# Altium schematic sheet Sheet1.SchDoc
size A3
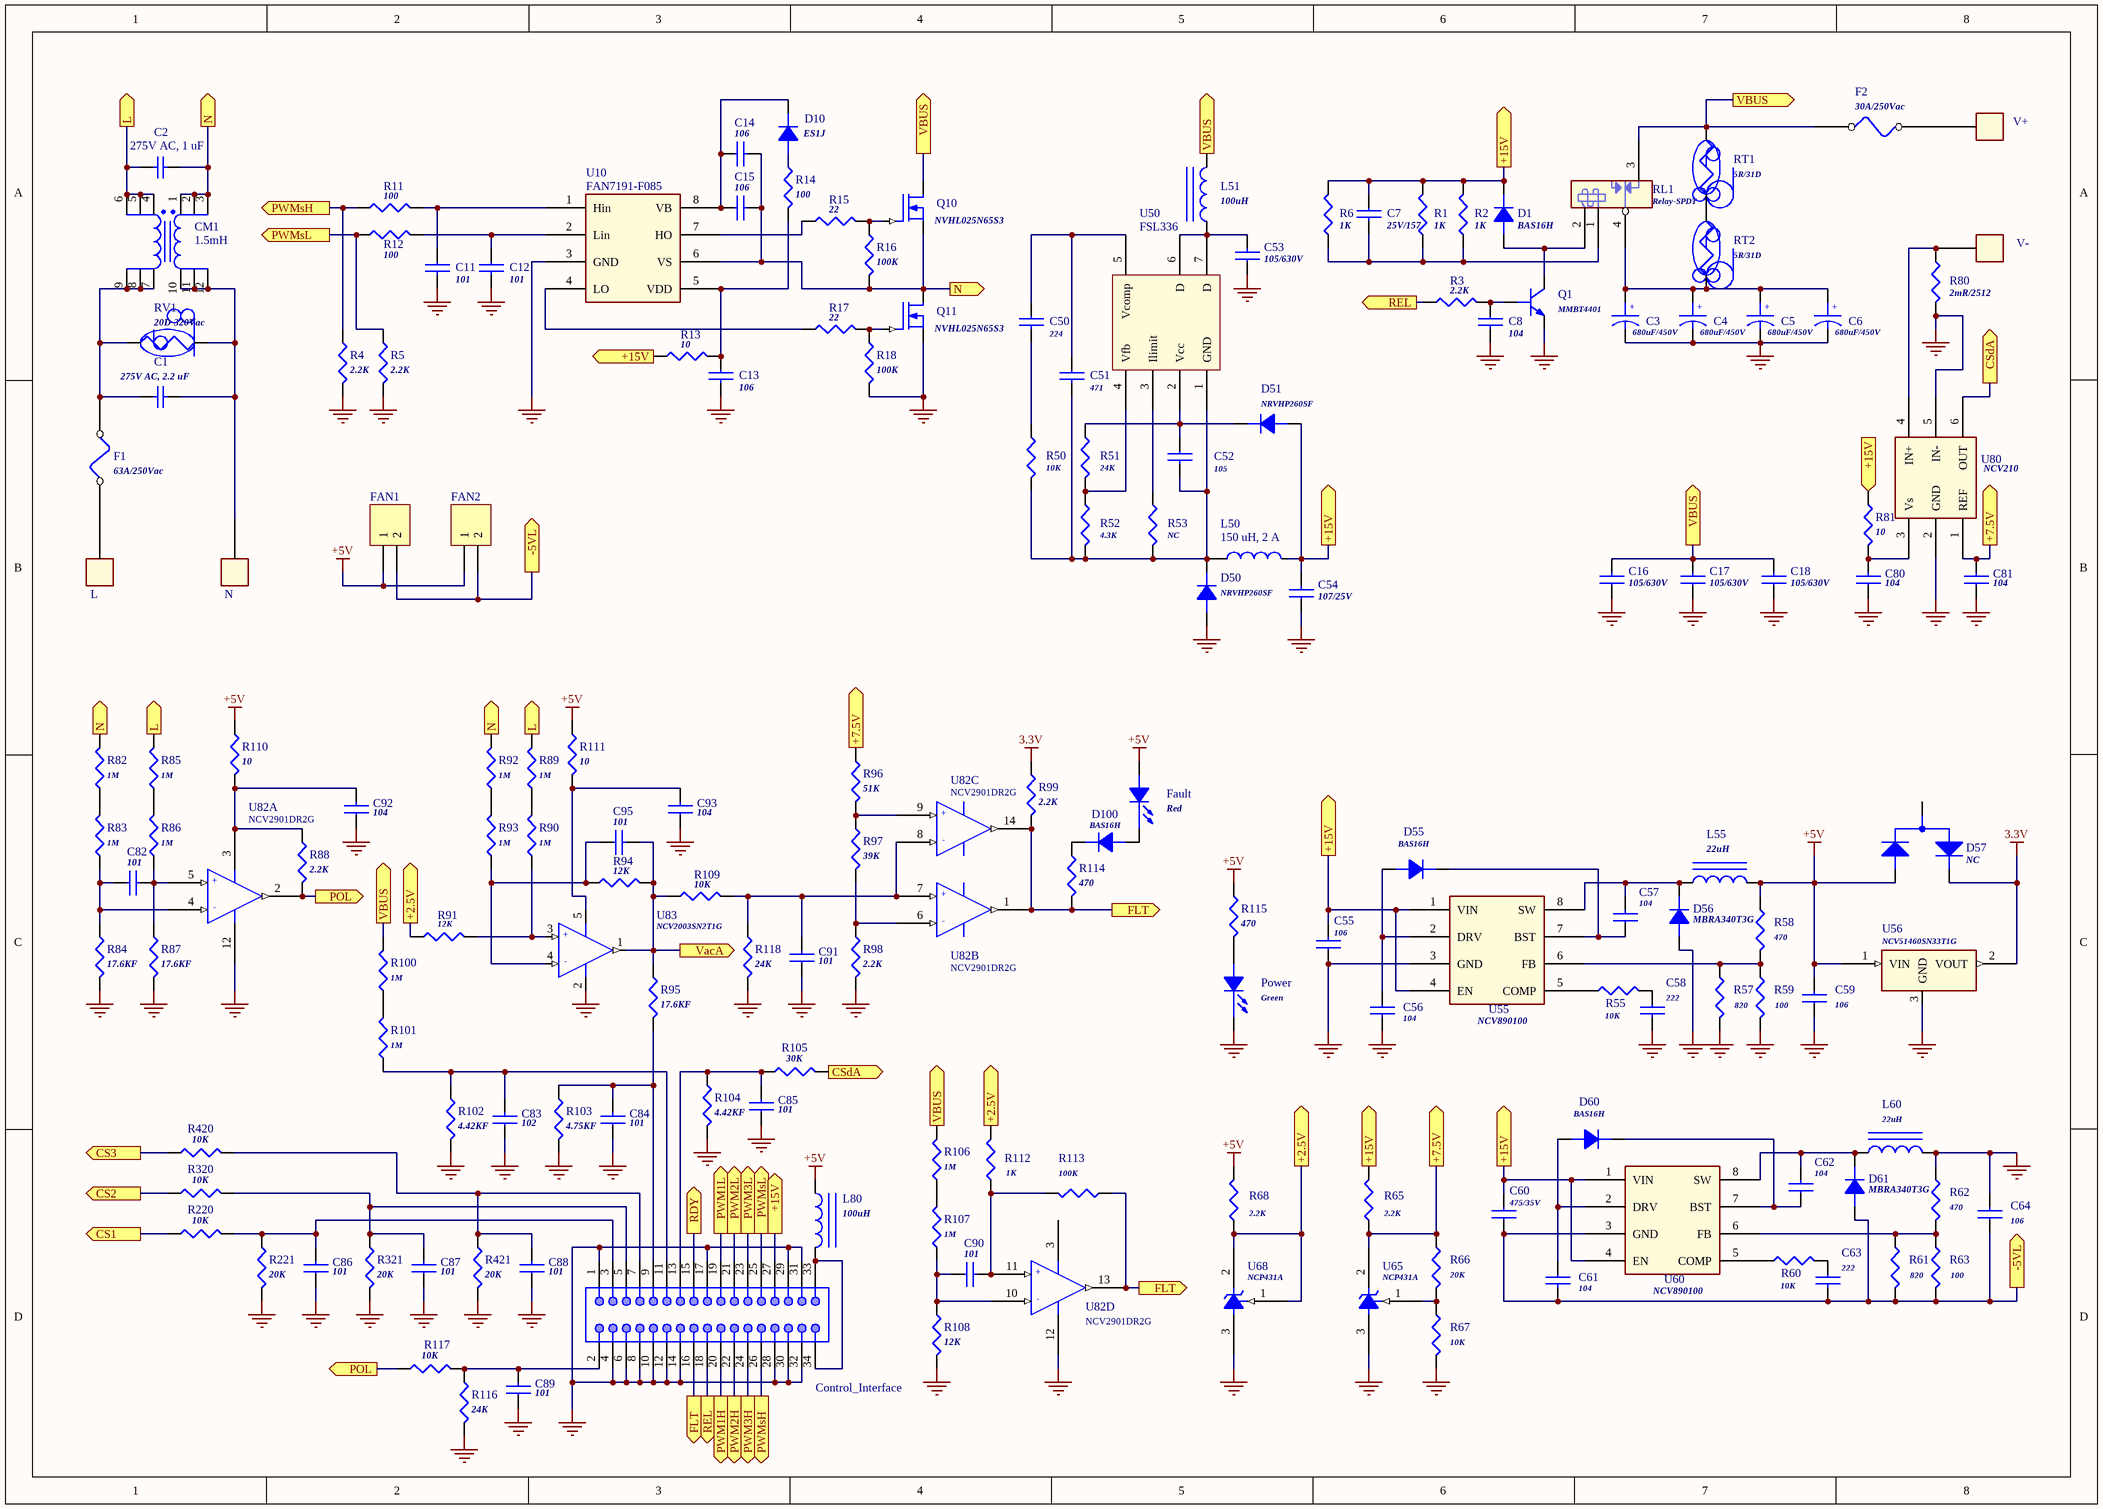
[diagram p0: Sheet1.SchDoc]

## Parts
C1  275V AC, 2.2 uF  [WCAP-FTX2_26x15x25_CS]
C2  275V AC, 1 uF  [WCAP-FTX2_26x11x20_CS]
C3  680uF/450V  [WCAP-AI3H_35x57]
C4  680uF/450V  [WCAP-AI3H_35x57]
C5  680uF/450V  [WCAP-AI3H_35x57]
C6  680uF/450V  [WCAP-AI3H_35x57]
C7  25V/157  [CAP2220_3]
C8  104  [SMT_0805_CM]
C11  101  [SMT_0805_CM]
C12  101  [SMT_0805_CM]
C13  106  [SMT_1206_CM]
C14  106  [SMT_1206_CM]
C15  106  [SMT_1206_CM]
C16  105/630V  [CAP2220]
C17  105/630V  [CAP2220]
C18  105/630V  [CAP2220]
C50  224  [SMT_0805_CM]
C51  471  [SMT_0805_CM]
C52  105  [SMT_0805_CM]
C53  105/630V  [CAP2220]
C54  107/25V  [CAP2220]
C55  106  [SMT_1206_CM]
C56  104  [SMT_0805_CM]
C57  104  [SMT_0805_CM]
C58  222  [SMT_0805_CM]
C59  106  [SMT_1206_CM]
C60  475/35V  [SMT_1206_CM]
C61  104  [SMT_0805_CM]
C62  104  [SMT_0805_CM]
C63  222  [SMT_0805_CM]
C64  106  [SMT_1206_CM]
C80  104  [SMT_0805_CM]
C81  104  [SMT_0805_CM]
C82  101  [SMT_0805_CM]
C83  102  [SMT_0805_CM]
C84  101  [SMT_0805_CM]
C85  101  [SMT_0805_CM]
C86  101  [SMT_0805_CM]
C87  101  [SMT_0805_CM]
C88  101  [SMT_0805_CM]
C89  101  [SMT_0805_CM]
C90  101  [SMT_0805_CM]
C91  101  [SMT_0805_CM]
C92  104  [SMT_0805_CM]
C93  104  [SMT_0805_CM]
C95  101  [SMT_0805_CM]
CM1  1.5mH  [L-WE-CMBNC_Type XXL_7448063801]
Control_Interface  (no value)  [61203421621]
D1  BAS16H  [SOD-323M]
D10  ES1J  [DO-214AC(SMA)]
D50  NRVHP260SF  [SOD-123FL]
D51  NRVHP260SF  [SOD-123FL]
D55  BAS16H  [SOD-323]
D56  MBRA340T3G  [DO-214AC(SMA)]
D57  NC  [SOT-23-3L]
D60  BAS16H  [SOD-323]
D61  MBRA340T3G  [DO-214AC(SMA)]
D100  BAS16H  [SOD-323]
F1  63A/250Vac  [Fuse_63A]
F2  30A/250Vac  [FUSE-L]
FAN1  Header 2  [XH-2A]  (value not drawn)
FAN2  Header 2  [XH-2A]  (value not drawn)
Fault  Red  [LED 5MM-R]
L  (no value)  [TermL]
L50  150 uH, 2 A  [WE-TI_1014_Standard]
L51  100uH  [Bead_1210]
L55  22uH  [INDUCTOR-7*7*3.5]
L60  22uH  [INDUCTOR-7*7*3.5]
L80  100uH  [Bead_1210]
N  (no value)  [TermL]
Power  Green  [LED 5MM-R]
Q1  MMBT4401  [SOT-23-3L]
Q10  NVHL025N65S3  [TO247]
Q11  NVHL025N65S3  [TO247]
R1  1K  [SMT_1206_RM]
R2  1K  [SMT_1206_RM]
R3  2.2K  [SMT_0805_RM]
R4  2.2K  [SMT_0805_RM]
R5  2.2K  [SMT_0805_RM]
R6  1K  [SMT_1206_RM]
R11  100  [SMT_0805_RM]
R12  100  [SMT_0805_RM]
R13  10  [SMT_0805_RM]
R14  100  [SMT_0805_RM]
R15  22  [SMT_0805_RM]
R16  100K  [SMT_0805_RM]
R17  22  [SMT_0805_RM]
R18  100K  [SMT_0805_RM]
R50  10K  [SMT_0805_RM]
R51  24K  [SMT_0805_RM]
R52  4.3K  [SMT_0805_RM]
R53  NC  [SMT_0805_RM]
R55  10K  [SMT_0805_RM]
R57  820  [SMT_0805_RM]
R58  470  [SMT_0805_RM]
R59  100  [SMT_0805_RM]
R60  10K  [SMT_0805_RM]
R61  820  [SMT_0805_RM]
R62  470  [SMT_0805_RM]
R63  100  [SMT_0805_RM]
R65  2.2K  [SMT_1206_RM]
R66  20K  [SMT_0805_RM]
R67  10K  [SMT_0805_RM]
R68  2.2K  [SMT_0805_RM]
R80  2mR/2512  [SMT_2512_R]
R81  10  [SMT_0805_RM]
R82  1M  [SMT_1206_RM]
R83  1M  [SMT_1206_RM]
R84  17.6KF  [SMT_0805_RM]
R85  1M  [SMT_1206_RM]
R86  1M  [SMT_1206_RM]
R87  17.6KF  [SMT_0805_RM]
R88  2.2K  [SMT_0805_RM]
R89  1M  [SMT_1206_RM]
R90  1M  [SMT_1206_RM]
R91  12K  [SMT_0805_RM]
R92  1M  [SMT_1206_RM]
R93  1M  [SMT_1206_RM]
R94  12K  [SMT_0805_RM]
R95  17.6KF  [SMT_0805_RM]
R96  51K  [SMT_0805_RM]
R97  39K  [SMT_0805_RM]
R98  2.2K  [SMT_0805_RM]
R99  2.2K  [SMT_0805_RM]
R100  1M  [SMT_1206_RM]
R101  1M  [SMT_1206_RM]
R102  4.42KF  [SMT_0805_RM]
R103  4.75KF  [SMT_0805_RM]
R104  4.42KF  [SMT_0805_RM]
R105  30K  [SMT_0805_RM]
R106  1M  [SMT_1206_RM]
R107  1M  [SMT_1206_RM]
R108  12K  [SMT_0805_RM]
R109  10K  [SMT_0805_RM]
R110  10  [SMT_0805_RM]
R111  10  [SMT_0805_RM]
R112  1K  [SMT_0805_RM]
R113  100K  [SMT_0805_RM]
R114  470  [SMT_0805_RM]
R115  470  [SMT_0805_RM]
R116  24K  [SMT_0805_RM]
R117  10K  [SMT_0805_RM]
R118  24K  [SMT_0805_RM]
R220  10K  [SMT_0805_RM]
R221  20K  [SMT_0805_RM]
R320  10K  [SMT_0805_RM]
R321  20K  [SMT_0805_RM]
R420  10K  [SMT_0805_RM]
R421  20K  [SMT_0805_RM]
RL1  Relay-SPDT  [Relay- SPST-25A]
RT1  5R/31D  [NTC-D31]
RT2  5R/31D  [NTC-D31]
RV1  20D-320Vac  [Thermistor-20mm-2]
U10  FAN7191-F085  [Sop8]
U50  FSL336  [DIP7]
U55  NCV890100  [SOIC8E]
U56  NCV51460SN33T1G  [SOT-23-3L]
U60  NCV890100  [SOIC8E]
U65  NCP431A  [SOT-23-3L]
U68  NCP431A  [SOT-23-3L]
U80  NCV210  [SC70-6]
U82  NCV2901DR2G  [SOP14]  (parts A,B,C,D of 4)
U83  NCV2003SN2T1G  [SOT-23-5L]
V+  (no value)  [TermL]
V-  (no value)  [TermL]

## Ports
+2.5V (out), +7.5V (out), +15V (out), -5VL (out), CS1 (out), CS2 (out), CS3 (out), CSdA (out), FLT (out), L (out), N (out), POL (out), PWM1H (out), PWM1L (out), PWM2H (out), PWM2L (out), PWM3H (out), PWM3L (out), PWMsH (out), PWMsL (out), RDY (out), REL (out), VacA (out), VBUS (out)

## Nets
3.3V: D57.2 R99.1 U56.2(VOUT)
+5V: C59.2 D57.1 FAN1.1 FAN2.1 Fault.1(ANODE) L55.2 L80.1 R58.1 R68.2 R110.1 R111.1 R115.1 U56.1(VIN)
PGND: C3.2 C4.2 C5.2 C6.2 C8.2 C11.2 C12.2 C13.2 C16.1 C17.1 C18.1 C53.1 C54.1 C55.1 C56.2 C58.2 C59.1 C64.2 C80.1 C81.1 C83.1 C84.1 C85.1 C86.1 C87.1 C88.1 C89.1 C91.1 C92.1 C93.1 Control_Interface.1 Control_Interface.4 Control_Interface.6 Control_Interface.8 Control_Interface.10 Control_Interface.12 Control_Interface.14 Control_Interface.17 Control_Interface.28 Control_Interface.29 Control_Interface.30 Control_Interface.31 Control_Interface.32 D50.1(A) D56.1(A) L60.2 Power.2(CATHODE) Q1.2(E) Q11.3(SOURCE) R4.2 R5.2 R18.2 R57.2 R59.2 R62.1 R67.2 R80.2 R84.2 R87.2 R98.2 R102.2 R103.2 R104.2 R108.2 R116.2 R118.2 R221.2 R321.2 R421.2 U10.3(GND) U55.3(GND) U56.3(GND) U65.3(A) U68.3(A) U80.2(GND) U80.5(IN-) U82.12(GND) U83.2(GND)
+2.5V: R68.1 R91.1 R112.2 U68.1(REF) U68.2(K) ; port +2.5V
+7.5V: C81.2 R65.1 R66.1 R96.1 U65.2(K) U80.1(REF) ; port +7.5V
+15V: C7.1 C54.2 C55.2 C60.2 Control_Interface.27 D1.2(K) D51.1(A) L50.2 R1.2 R2.2 R6.2 R13.1 R65.2 R81.1 U55.1(VIN) U55.4(EN) U60.1(VIN) U60.4(EN) ; port +15V
-5VL: C60.1 C61.2 C63.2 C64.1 D61.1(A) FAN1.2 FAN2.2 R61.2 R63.2 U60.3(GND) ; port -5VL
CS1: R220.1 ; port CS1
CS2: R320.1 ; port CS2
CS3: R420.1 ; port CS3
CSdA: R105.2 U80.6(OUT) ; port CSdA
FLT: Control_Interface.16 R99.2 R113.1 R114.2 U82.1(OUT) U82.13(OUT) U82.14(OUT) ; port FLT
L: C2.2 CM1.4 CM1.5 CM1.6 R85.2 R89.2 ; port L
N: C2.1 C14.2 C15.2 CM1.1 CM1.2 CM1.3 Q10.3(SOURCE) Q11.2(DRAIN) R16.2 R82.2 R92.2 U10.6(VS) ; port N
POL: R88.2 R117.1 U82.2(OUT) ; port POL
PWM1H: Control_Interface.20 ; port PWM1H
PWM1L: Control_Interface.19 ; port PWM1L
PWM2H: Control_Interface.22 ; port PWM2H
PWM2L: Control_Interface.21 ; port PWM2L
PWM3H: Control_Interface.24 ; port PWM3H
PWM3L: Control_Interface.23 ; port PWM3L
PWMsH: Control_Interface.26 R4.1 R11.1 ; port PWMsH
PWMsL: Control_Interface.25 R5.1 R12.1 ; port PWMsL
RDY: Control_Interface.15 ; port RDY
REL: Control_Interface.18 R3.1 ; port REL
VacA: C95.2 R94.2 R95.1 R109.1 U83.1(OUT) ; port VacA
VBUS: C16.2 C17.2 C18.2 F2.1 L51.2 Q10.2(DRAIN) R100.2 R106.2 RL1.3(NO) RT1.1 ; port VBUS
NetC1_1: C1.1 CM1.10 CM1.11 CM1.12 N.1 RV1.2
NetC1_2: C1.2 CM1.7 CM1.8 CM1.9 F1.1 RV1.1
NetC3_1: C3.1 C4.1 C5.1 C6.1 RL1.4(COMMON) RT2.2
NetC7_2: C7.2 R1.1 R2.1 R6.1 RL1.1(COIL1)
NetC8_1: C8.1 Q1.1(B) R3.2
NetC11_1: C11.1 R11.2 U10.1(Hin)
NetC12_1: C12.1 R12.2 U10.2(Lin)
NetC13_1: C13.1 R13.2 R14.2 U10.5(VDD)
NetC14_1: C14.1 C15.1 D10.2(K) U10.8(VB)
NetC50_1: C50.1 C51.1 U50.5(Vcomp)
NetC50_2: C50.2 R50.1
NetC51_2: C51.2 C52.2 D50.2(K) L50.1 R50.2 R52.2 R53.2 U50.1(GND)
NetC52_1: C52.1 D51.2(K) R51.1 U50.2(Vcc)
NetC53_2: C53.2 L51.1 U50.6(D) U50.7(D)
NetC56_1: C56.1 D55.1(A) U55.2(DRV)
NetC57_1: C57.1 D55.2(K) U55.7(BST)
NetC57_2: C57.2 D56.2(K) L55.1 U55.8(SW)
NetC58_1: C58.1 R55.2
NetC61_1: C61.1 D60.1(A) U60.2(DRV)
NetC62_1: C62.1 D60.2(K) U60.7(BST)
NetC62_2: C62.2 D61.2(K) L60.1 U60.8(SW)
NetC63_1: C63.1 R60.2
NetC80_2: C80.2 R81.2 U80.3(Vs)
NetC82_1: C82.1 R83.1 R84.1 U82.4(-IN)
NetC82_2: C82.2 R86.1 R87.1 U82.5(+IN)
NetC83_2: C83.2 Control_Interface.11 R101.1 R102.1
NetC84_2: C84.2 Control_Interface.9 R95.2 R103.1
NetC85_2: C85.2 Control_Interface.13 R104.1 R105.1
NetC86_2: C86.2 Control_Interface.3 R220.2 R221.1
NetC87_2: C87.2 Control_Interface.5 R320.2 R321.1
NetC88_2: C88.2 Control_Interface.7 R420.2 R421.1
NetC89_2: C89.2 Control_Interface.2 R116.1 R117.2
NetC90_1: C90.1 R107.1 R108.1 U82.10(-IN)
NetC90_2: C90.2 R112.1 R113.2 U82.11(+IN)
NetC91_2: C91.2 R109.2 R118.1 U82.7(+IN) U82.8(-IN)
NetC92_2: C92.2 R88.1 R110.2 U82.3(VCC)
NetC93_2: C93.2 R111.2 U83.5(VCC)
NetC95_1: C95.1 R93.1 R94.1 U83.4(-IN)
NetControl_Interface_33: Control_Interface.33 Control_Interface.34 L80.2
NetD1_1: D1.1(A) Q1.3(C) RL1.2(COIL2)
NetD10_1: D10.1(A) R14.1
NetD100_1: D100.1(A) Fault.2(CATHODE)
NetD100_2: D100.2(K) R114.1
NetF1_2: F1.2 L.1
NetF2_2: F2.2 V+.1
NetPower_1: Power.1(ANODE) R115.2
NetQ10_1: Q10.1(GATE) R15.2 R16.1
NetQ11_1: Q11.1(GATE) R17.2 R18.1
NetR15_1: R15.1 U10.7(HO)
NetR17_1: R17.1 U10.4(LO)
NetR51_2: R51.2 R52.1 U50.4(Vfb)
NetR53_1: R53.1 U50.3(Ilimit)
NetR55_1: R55.1 U55.5(COMP)
NetR57_1: R57.1 R58.2 R59.1 U55.6(FB)
NetR60_1: R60.1 U60.5(COMP)
NetR61_1: R61.1 R62.2 R63.1 U60.6(FB)
NetR66_2: R66.2 R67.1 U65.1(REF)
NetR80_1: R80.1 U80.4(IN+) V-.1
NetR82_1: R82.1 R83.2
NetR85_1: R85.1 R86.2
NetR89_1: R89.1 R90.2
NetR90_1: R90.1 R91.2 U83.3(+IN)
NetR92_1: R92.1 R93.2
NetR96_2: R96.2 R97.1 U82.9(+IN)
NetR97_2: R97.2 R98.1 U82.6(-IN)
NetR100_1: R100.1 R101.2
NetR106_1: R106.1 R107.2
NetRT1_2: RT1.2 RT2.1

Not connected (* = marked no-connect by the designer): D57 3

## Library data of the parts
C1 = 890324026034CS: WCAP-FTX2 Film Capacitors, 26x15x25mm, 275V AC, 2.2 uF; Rated Voltage: 275V AC; Value: 2.2 uF
C2 = 890324026027CS: WCAP-FTX2 Film Capacitors, 26x11x20mm, 275V AC, 1 uF; Rated Voltage: 275V AC; Value: 1 uF
C3-C6 = CAP POL
C7 C8 C11-C18 C50-C64 C82 C90 C95 = CAP NP
C80 C81 C83-C89 C91-C93 = CAP_0805
CM1 = WE-CMBNC, 7448063801: WE-CMBNC Common Mode Power Line Choke Nanocrystalline, Type XXL, 1.5mH
Control_Interface = 61203421621: Male Box Header WR-BHD, THT, Vertical, pitch 2.54 mm, 34 pins; Pin Number: 34; Pitch: 2.54 mm; Working Voltage: 250 VAC; Withstanding Voltage: 500 VAC; Contact Resistance: 20 mOhm
D1 D50 D51 D55 D56 D60 D61 D100 = DIODE
D10 = D_SMA(DO-214AC)
D57 = BAT54S/SOT
F1 F2 = FUSE
FAN1 FAN2 = Header 2: Header, 2-Pin
Fault Power = LED
L N V+ V- = P_1
L50 = 7447480151: Radial Leaded Wire Wound Inductor WE-TI, size 1014, 150 uH, 2 A; Rated Current: 2 A; Inductance: 150 uH; DC Resistance max.: 0.18 Ohm; Self Resonant Frequency: 3.1 MHz; Saturation Current: 2.1 A; Type: Standard
L51 L55 L60 L80 = INDUCTOR IRON
Q1 = NPN BCE
Q10 Q11 = MOSFET N: NTPF082N65S3F; R187: C158
R1-R6 R11-R18 R55 R57-R63 R65-R68 R80-R104 R106-R116 R118 R221 R321 R421 = R
R50-R53 = R: D5: L20
R105 R117 R220 R320 R420 = R_0805
RL1 = RELAY SPDT
RT1 RT2 = NTC_0
RV1 = R_NTC_20MM
U10 = FAN7191F
U55 U60 = NCV890200
U56 = 78HT2
U65 U68 = TL431
U82 = LM339
U83 = LM383/TO220_1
